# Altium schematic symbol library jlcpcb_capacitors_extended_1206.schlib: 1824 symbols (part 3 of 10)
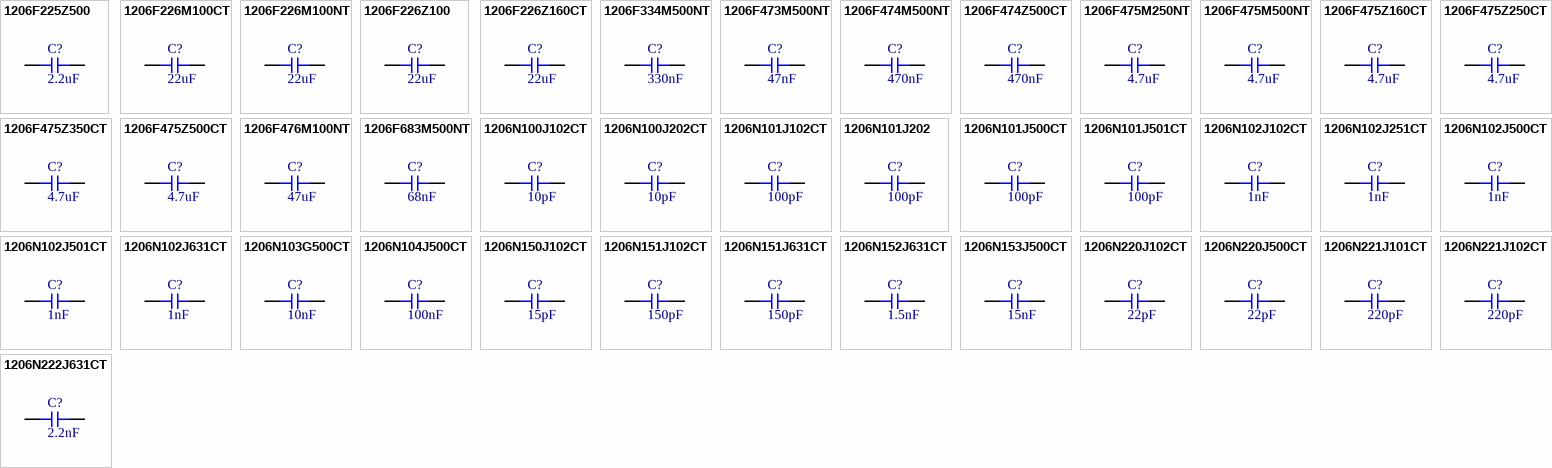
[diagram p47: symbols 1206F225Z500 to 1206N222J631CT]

## 1206N221J101CT
designator C?  Capacitance: 220pF  (hidden comment: *)
Capacitor, Ceramic (MLCC), 220pF, ±5%, 100V, NP0, ±5%, SMD 1206; Manufacturer: Walsin Tech Corp; Manufacturer Part Number: 1206N221J101CT
footprint CAP-1206 (1206 (3216M) Capacitor)
pins: 1, 2

## 1206N221J102CT
designator C?  Capacitance: 220pF  (hidden comment: *)
Capacitor, Ceramic (MLCC), 220pF, ±5%, 1kV, NP0, ±5%, SMD 1206; Manufacturer: Walsin Tech Corp; Manufacturer Part Number: 1206N221J102CT
footprint CAP-1206 (1206 (3216M) Capacitor)
pins: 1, 2

## 1206N222J631CT
designator C?  Capacitance: 2.2nF  (hidden comment: *)
Capacitor, Ceramic (MLCC), 2.2nF, ±5%, 630V, NP0, ±5%, SMD 1206; Manufacturer: Walsin Tech Corp; Manufacturer Part Number: 1206N222J631CT
footprint CAP-1206 (1206 (3216M) Capacitor)
pins: 1, 2

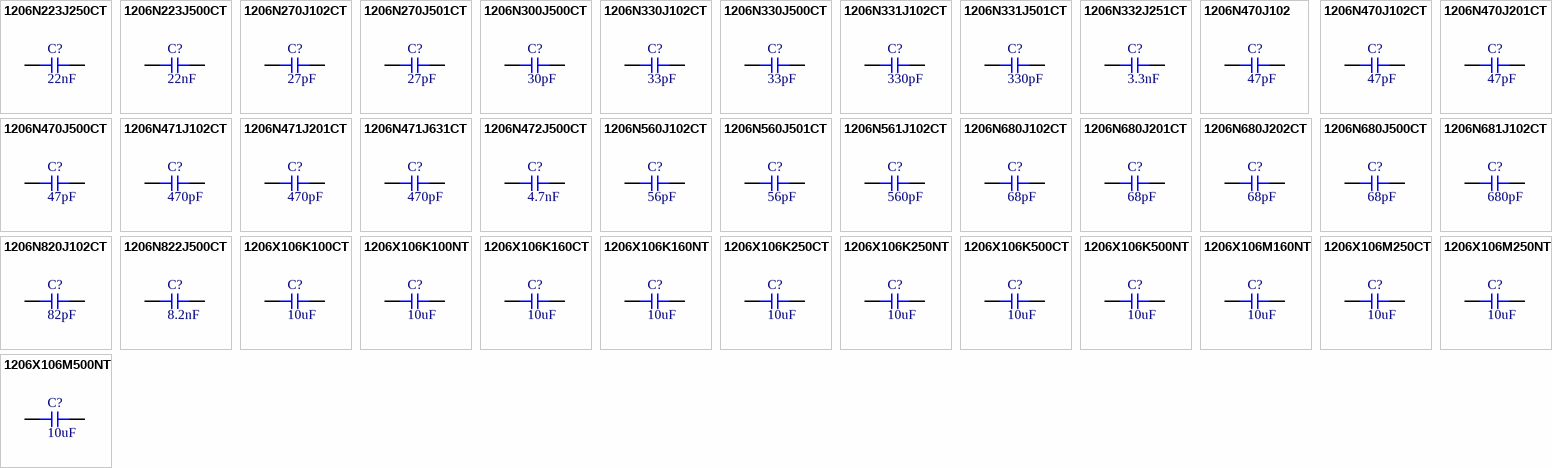
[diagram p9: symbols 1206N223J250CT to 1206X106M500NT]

## 1206N223J250CT
designator C?  Capacitance: 22nF  (hidden comment: *)
Capacitor, Ceramic (MLCC), 22nF, ±5%, 25V, NP0, ±5%, SMD 1206; Manufacturer: Walsin Tech Corp; Manufacturer Part Number: 1206N223J250CT
footprint CAP-1206 (1206 (3216M) Capacitor)
pins: 1, 2

## 1206N223J500CT
designator C?  Capacitance: 22nF  (hidden comment: *)
Capacitor, Ceramic (MLCC), 22nF, ±5%, 50V, NP0, ±5%, SMD 1206; Manufacturer: Walsin Tech Corp; Manufacturer Part Number: 1206N223J500CT
footprint CAP-1206 (1206 (3216M) Capacitor)
pins: 1, 2

## 1206N270J102CT
designator C?  Capacitance: 27pF  (hidden comment: *)
Capacitor, Ceramic (MLCC), 27pF, ±5%, 1kV, NP0, ±5%, SMD 1206; Manufacturer: Walsin Tech Corp; Manufacturer Part Number: 1206N270J102CT
footprint CAP-1206 (1206 (3216M) Capacitor)
pins: 1, 2

## 1206N270J501CT
designator C?  Capacitance: 27pF  (hidden comment: *)
Capacitor, Ceramic (MLCC), 27pF, ±5%, 500V, NP0, ±5%, SMD 1206; Manufacturer: Walsin Tech Corp; Manufacturer Part Number: 1206N270J501CT
footprint CAP-1206 (1206 (3216M) Capacitor)
pins: 1, 2

## 1206N300J500CT
designator C?  Capacitance: 30pF  (hidden comment: *)
Capacitor, Ceramic (MLCC), 30pF, ±5%, 50V, NP0, ±5%, SMD 1206; Manufacturer: Walsin Tech Corp; Manufacturer Part Number: 1206N300J500CT
footprint CAP-1206 (1206 (3216M) Capacitor)
pins: 1, 2

## 1206N330J102CT
designator C?  Capacitance: 33pF  (hidden comment: *)
Capacitor, Ceramic (MLCC), 33pF, ±5%, 1kV, NP0, ±5%, SMD 1206; Manufacturer: Walsin Tech Corp; Manufacturer Part Number: 1206N330J102CT
footprint CAP-1206 (1206 (3216M) Capacitor)
pins: 1, 2

## 1206N330J500CT
designator C?  Capacitance: 33pF  (hidden comment: *)
Capacitor, Ceramic (MLCC), 33pF, ±5%, 50V, NP0, ±5%, SMD 1206; Manufacturer: Walsin Tech Corp; Manufacturer Part Number: 1206N330J500CT
footprint CAP-1206 (1206 (3216M) Capacitor)
pins: 1, 2

## 1206N331J102CT
designator C?  Capacitance: 330pF  (hidden comment: *)
Capacitor, Ceramic (MLCC), 330pF, ±5%, 1kV, NP0, ±5%, SMD 1206; Manufacturer: Walsin Tech Corp; Manufacturer Part Number: 1206N331J102CT
footprint CAP-1206 (1206 (3216M) Capacitor)
pins: 1, 2

## 1206N331J501CT
designator C?  Capacitance: 330pF  (hidden comment: *)
Capacitor, Ceramic (MLCC), 330pF, ±5%, 500V, NP0, ±5%, SMD 1206; Manufacturer: Walsin Tech Corp; Manufacturer Part Number: 1206N331J501CT
footprint CAP-1206 (1206 (3216M) Capacitor)
pins: 1, 2

## 1206N332J251CT
designator C?  Capacitance: 3.3nF  (hidden comment: *)
Capacitor, Ceramic (MLCC), 3.3nF, ±5%, 250V, NP0, ±5%, SMD 1206; Manufacturer: Walsin Tech Corp; Manufacturer Part Number: 1206N332J251CT
footprint CAP-1206 (1206 (3216M) Capacitor)
pins: 1, 2

## 1206N470J102
designator C?  Capacitance: 47pF  (hidden comment: *)
Capacitor, Ceramic (MLCC), 47pF, ±5%, 1kV, NP0, ±5%, SMD 1206; Manufacturer: Walsin Tech Corp; Manufacturer Part Number: 1206N470J102
footprint CAP-1206 (1206 (3216M) Capacitor)
pins: 1, 2

## 1206N470J102CT
designator C?  Capacitance: 47pF  (hidden comment: *)
Capacitor, Ceramic (MLCC), 47pF, ±5%, 1kV, NP0, ±5%, SMD 1206; Manufacturer: Walsin Tech Corp; Manufacturer Part Number: 1206N470J102CT
footprint CAP-1206 (1206 (3216M) Capacitor)
pins: 1, 2

## 1206N470J201CT
designator C?  Capacitance: 47pF  (hidden comment: *)
Capacitor, Ceramic (MLCC), 47pF, ±5%, 200V, NP0, ±5%, SMD 1206; Manufacturer: Walsin Tech Corp; Manufacturer Part Number: 1206N470J201CT
footprint CAP-1206 (1206 (3216M) Capacitor)
pins: 1, 2

## 1206N470J500CT
designator C?  Capacitance: 47pF  (hidden comment: *)
Capacitor, Ceramic (MLCC), 47pF, ±5%, 50V, NP0, ±5%, SMD 1206; Manufacturer: Walsin Tech Corp; Manufacturer Part Number: 1206N470J500CT
footprint CAP-1206 (1206 (3216M) Capacitor)
pins: 1, 2

## 1206N471J102CT
designator C?  Capacitance: 470pF  (hidden comment: *)
Capacitor, Ceramic (MLCC), 470pF, ±5%, 1kV, NP0, ±5%, SMD 1206; Manufacturer: Walsin Tech Corp; Manufacturer Part Number: 1206N471J102CT
footprint CAP-1206 (1206 (3216M) Capacitor)
pins: 1, 2

## 1206N471J201CT
designator C?  Capacitance: 470pF  (hidden comment: *)
Capacitor, Ceramic (MLCC), 470pF, ±5%, 200V, NP0, ±5%, SMD 1206; Manufacturer: Walsin Tech Corp; Manufacturer Part Number: 1206N471J201CT
footprint CAP-1206 (1206 (3216M) Capacitor)
pins: 1, 2

## 1206N471J631CT
designator C?  Capacitance: 470pF  (hidden comment: *)
Capacitor, Ceramic (MLCC), 470pF, ±5%, 630V, NP0, ±5%, SMD 1206; Manufacturer: Walsin Tech Corp; Manufacturer Part Number: 1206N471J631CT
footprint CAP-1206 (1206 (3216M) Capacitor)
pins: 1, 2

## 1206N472J500CT
designator C?  Capacitance: 4.7nF  (hidden comment: *)
Capacitor, Ceramic (MLCC), 4.7nF, ±5%, 50V, NP0, ±5%, SMD 1206; Manufacturer: Walsin Tech Corp; Manufacturer Part Number: 1206N472J500CT
footprint CAP-1206 (1206 (3216M) Capacitor)
pins: 1, 2

## 1206N560J102CT
designator C?  Capacitance: 56pF  (hidden comment: *)
Capacitor, Ceramic (MLCC), 56pF, ±5%, 1kV, NP0, ±5%, SMD 1206; Manufacturer: Walsin Tech Corp; Manufacturer Part Number: 1206N560J102CT
footprint CAP-1206 (1206 (3216M) Capacitor)
pins: 1, 2

## 1206N560J501CT
designator C?  Capacitance: 56pF  (hidden comment: *)
Capacitor, Ceramic (MLCC), 56pF, ±5%, 500V, NP0, ±5%, SMD 1206; Manufacturer: Walsin Tech Corp; Manufacturer Part Number: 1206N560J501CT
footprint CAP-1206 (1206 (3216M) Capacitor)
pins: 1, 2

## 1206N561J102CT
designator C?  Capacitance: 560pF  (hidden comment: *)
Capacitor, Ceramic (MLCC), 560pF, ±5%, 1kV, NP0, ±5%, SMD 1206; Manufacturer: Walsin Tech Corp; Manufacturer Part Number: 1206N561J102CT
footprint CAP-1206 (1206 (3216M) Capacitor)
pins: 1, 2

## 1206N680J102CT
designator C?  Capacitance: 68pF  (hidden comment: *)
Capacitor, Ceramic (MLCC), 68pF, ±5%, 1kV, NP0, ±5%, SMD 1206; Manufacturer: Walsin Tech Corp; Manufacturer Part Number: 1206N680J102CT
footprint CAP-1206 (1206 (3216M) Capacitor)
pins: 1, 2

## 1206N680J201CT
designator C?  Capacitance: 68pF  (hidden comment: *)
Capacitor, Ceramic (MLCC), 68pF, ±5%, 200V, NP0, ±5%, SMD 1206; Manufacturer: Walsin Tech Corp; Manufacturer Part Number: 1206N680J201CT
footprint CAP-1206 (1206 (3216M) Capacitor)
pins: 1, 2

## 1206N680J202CT
designator C?  Capacitance: 68pF  (hidden comment: *)
Capacitor, Ceramic (MLCC), 68pF, ±5%, 2kV, NP0, ±5%, SMD 1206; Manufacturer: Walsin Tech Corp; Manufacturer Part Number: 1206N680J202CT
footprint CAP-1206 (1206 (3216M) Capacitor)
pins: 1, 2

## 1206N680J500CT
designator C?  Capacitance: 68pF  (hidden comment: *)
Capacitor, Ceramic (MLCC), 68pF, ±5%, 50V, NP0, ±5%, SMD 1206; Manufacturer: Walsin Tech Corp; Manufacturer Part Number: 1206N680J500CT
footprint CAP-1206 (1206 (3216M) Capacitor)
pins: 1, 2

## 1206N681J102CT
designator C?  Capacitance: 680pF  (hidden comment: *)
Capacitor, Ceramic (MLCC), 680pF, ±5%, 1kV, NP0, ±5%, SMD 1206; Manufacturer: Walsin Tech Corp; Manufacturer Part Number: 1206N681J102CT
footprint CAP-1206 (1206 (3216M) Capacitor)
pins: 1, 2

## 1206N820J102CT
designator C?  Capacitance: 82pF  (hidden comment: *)
Capacitor, Ceramic (MLCC), 82pF, ±5%, 1kV, NP0, ±5%, SMD 1206; Manufacturer: Walsin Tech Corp; Manufacturer Part Number: 1206N820J102CT
footprint CAP-1206 (1206 (3216M) Capacitor)
pins: 1, 2

## 1206N822J500CT
designator C?  Capacitance: 8.2nF  (hidden comment: *)
Capacitor, Ceramic (MLCC), 8.2nF, ±5%, 50V, NP0, ±5%, SMD 1206; Manufacturer: Walsin Tech Corp; Manufacturer Part Number: 1206N822J500CT
footprint CAP-1206 (1206 (3216M) Capacitor)
pins: 1, 2

## 1206X106K100CT
designator C?  Capacitance: 10uF  (hidden comment: *)
Capacitor, Ceramic (MLCC), 10uF, ±10%, 10V, X5R, ±10%, SMD 1206; Manufacturer: Walsin Tech Corp; Manufacturer Part Number: 1206X106K100CT
footprint CAP-1206 (1206 (3216M) Capacitor)
pins: 1, 2

## 1206X106K100NT
designator C?  Capacitance: 10uF  (hidden comment: *)
Capacitor, Ceramic (MLCC), 10uF, ±10%, 10V, X5R, ±10%, SMD 1206; Manufacturer: FH(Guangdong Fenghua Advanced Tech); Manufacturer Part Number: 1206X106K100NT
footprint CAP-1206 (1206 (3216M) Capacitor)
pins: 1, 2

## 1206X106K160CT
designator C?  Capacitance: 10uF  (hidden comment: *)
Capacitor, Ceramic (MLCC), 10uF, ±10%, 16V, X5R, ±10%, SMD 1206; Manufacturer: Walsin Tech Corp; Manufacturer Part Number: 1206X106K160CT
footprint CAP-1206 (1206 (3216M) Capacitor)
pins: 1, 2

## 1206X106K160NT
designator C?  Capacitance: 10uF  (hidden comment: *)
Capacitor, Ceramic (MLCC), 10uF, ±10%, 16V, X5R, ±10%, SMD 1206; Manufacturer: FH(Guangdong Fenghua Advanced Tech); Manufacturer Part Number: 1206X106K160NT
footprint CAP-1206 (1206 (3216M) Capacitor)
pins: 1, 2

## 1206X106K250CT
designator C?  Capacitance: 10uF  (hidden comment: *)
Capacitor, Ceramic (MLCC), 10uF, ±10%, 25V, X5R, ±10%, SMD 1206; Manufacturer: Walsin Tech Corp; Manufacturer Part Number: 1206X106K250CT
footprint CAP-1206 (1206 (3216M) Capacitor)
pins: 1, 2

## 1206X106K250NT
designator C?  Capacitance: 10uF  (hidden comment: *)
Capacitor, Ceramic (MLCC), 10uF, ±10%, 25V, X5R, ±10%, SMD 1206; Manufacturer: FH(Guangdong Fenghua Advanced Tech); Manufacturer Part Number: 1206X106K250NT
footprint CAP-1206 (1206 (3216M) Capacitor)
pins: 1, 2

## 1206X106K500CT
designator C?  Capacitance: 10uF  (hidden comment: *)
Capacitor, Ceramic (MLCC), 10uF, ±10%, 50V, X5R, ±10%, SMD 1206; Manufacturer: Walsin Tech Corp; Manufacturer Part Number: 1206X106K500CT
footprint CAP-1206 (1206 (3216M) Capacitor)
pins: 1, 2

## 1206X106K500NT
designator C?  Capacitance: 10uF  (hidden comment: *)
Capacitor, Ceramic (MLCC), 10uF, ±10%, 50V, X5R, ±10%, SMD 1206; Manufacturer: FH(Guangdong Fenghua Advanced Tech); Manufacturer Part Number: 1206X106K500NT
footprint CAP-1206 (1206 (3216M) Capacitor)
pins: 1, 2

## 1206X106M160NT
designator C?  Capacitance: 10uF  (hidden comment: *)
Capacitor, Ceramic (MLCC), 10uF, ±20%, 16V, X5R, ±20%, SMD 1206; Manufacturer: FH(Guangdong Fenghua Advanced Tech); Manufacturer Part Number: 1206X106M160NT
footprint CAP-1206 (1206 (3216M) Capacitor)
pins: 1, 2

## 1206X106M250CT
designator C?  Capacitance: 10uF  (hidden comment: *)
Capacitor, Ceramic (MLCC), 10uF, ±20%, 25V, X5R, ±20%, SMD 1206; Manufacturer: Walsin Tech Corp; Manufacturer Part Number: 1206X106M250CT
footprint CAP-1206 (1206 (3216M) Capacitor)
pins: 1, 2

## 1206X106M250NT
designator C?  Capacitance: 10uF  (hidden comment: *)
Capacitor, Ceramic (MLCC), 10uF, ±20%, 25V, X5R, ±20%, SMD 1206; Manufacturer: FH(Guangdong Fenghua Advanced Tech); Manufacturer Part Number: 1206X106M250NT
footprint CAP-1206 (1206 (3216M) Capacitor)
pins: 1, 2

## 1206X106M500NT
designator C?  Capacitance: 10uF  (hidden comment: *)
Capacitor, Ceramic (MLCC), 10uF, ±20%, 50V, X5R, ±20%, SMD 1206; Manufacturer: FH(Guangdong Fenghua Advanced Tech); Manufacturer Part Number: 1206X106M500NT
footprint CAP-1206 (1206 (3216M) Capacitor)
pins: 1, 2

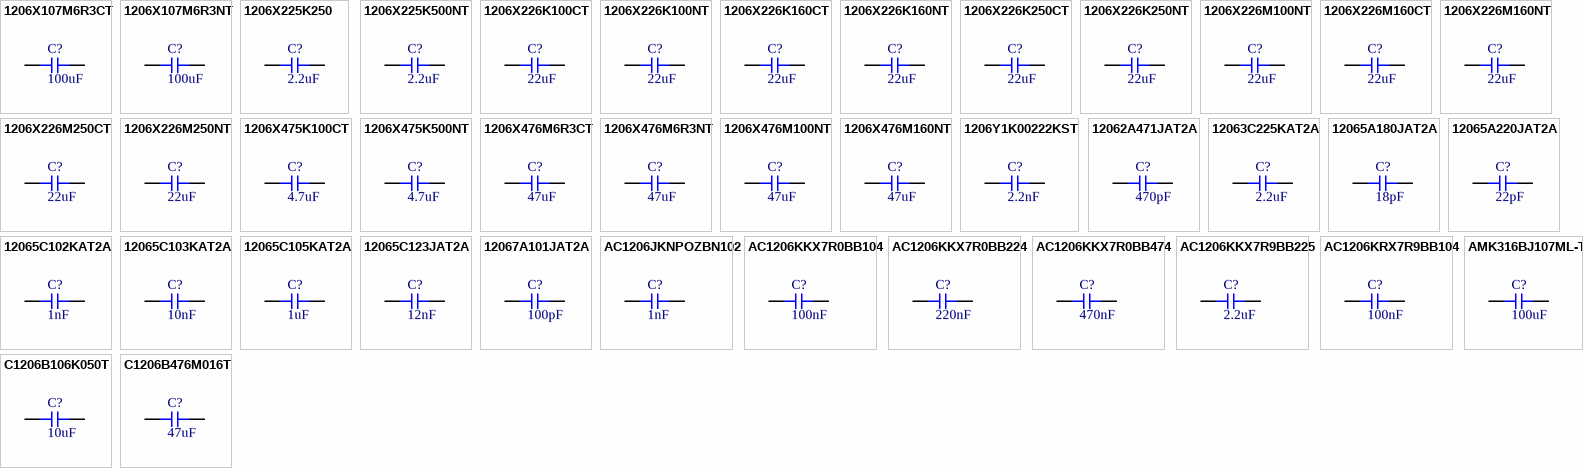
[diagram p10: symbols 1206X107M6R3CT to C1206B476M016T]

## 1206X107M6R3CT
designator C?  Capacitance: 100uF  (hidden comment: *)
Capacitor, Ceramic (MLCC), 100uF, ±20%, 6.3V, X5R, ±20%, SMD 1206; Manufacturer: Walsin Tech Corp; Manufacturer Part Number: 1206X107M6R3CT
footprint CAP-1206 (1206 (3216M) Capacitor)
pins: 1, 2

## 1206X107M6R3NT
designator C?  Capacitance: 100uF  (hidden comment: *)
Capacitor, Ceramic (MLCC), 100uF, ±20%, 6.3V, X5R, ±20%, SMD 1206; Manufacturer: FH(Guangdong Fenghua Advanced Tech); Manufacturer Part Number: 1206X107M6R3NT
footprint CAP-1206 (1206 (3216M) Capacitor)
pins: 1, 2

## 1206X225K250
designator C?  Capacitance: 2.2uF  (hidden comment: *)
Capacitor, Ceramic (MLCC), 2.2uF, ±10%, 25V, X5R, ±10%, SMD 1206; Manufacturer: Walsin Tech Corp; Manufacturer Part Number: 1206X225K250
footprint CAP-1206 (1206 (3216M) Capacitor)
pins: 1, 2

## 1206X225K500NT
designator C?  Capacitance: 2.2uF  (hidden comment: *)
Capacitor, Ceramic (MLCC), 2.2uF, ±10%, 50V, X5R, ±10%, SMD 1206; Manufacturer: FH(Guangdong Fenghua Advanced Tech); Manufacturer Part Number: 1206X225K500NT
footprint CAP-1206 (1206 (3216M) Capacitor)
pins: 1, 2

## 1206X226K100CT
designator C?  Capacitance: 22uF  (hidden comment: *)
Capacitor, Ceramic (MLCC), 22uF, ±10%, 10V, X5R, ±10%, SMD 1206; Manufacturer: Walsin Tech Corp; Manufacturer Part Number: 1206X226K100CT
footprint CAP-1206 (1206 (3216M) Capacitor)
pins: 1, 2

## 1206X226K100NT
designator C?  Capacitance: 22uF  (hidden comment: *)
Capacitor, Ceramic (MLCC), 22uF, ±10%, 10V, X5R, ±10%, SMD 1206; Manufacturer: FH(Guangdong Fenghua Advanced Tech); Manufacturer Part Number: 1206X226K100NT
footprint CAP-1206 (1206 (3216M) Capacitor)
pins: 1, 2

## 1206X226K160CT
designator C?  Capacitance: 22uF  (hidden comment: *)
Capacitor, Ceramic (MLCC), 22uF, ±10%, 16V, X5R, ±10%, SMD 1206; Manufacturer: Walsin Tech Corp; Manufacturer Part Number: 1206X226K160CT
footprint CAP-1206 (1206 (3216M) Capacitor)
pins: 1, 2

## 1206X226K160NT
designator C?  Capacitance: 22uF  (hidden comment: *)
Capacitor, Ceramic (MLCC), 22uF, ±10%, 16V, X5R, ±10%, SMD 1206; Manufacturer: FH(Guangdong Fenghua Advanced Tech); Manufacturer Part Number: 1206X226K160NT
footprint CAP-1206 (1206 (3216M) Capacitor)
pins: 1, 2

## 1206X226K250CT
designator C?  Capacitance: 22uF  (hidden comment: *)
Capacitor, Ceramic (MLCC), 22uF, ±10%, 25V, X5R, ±10%, SMD 1206; Manufacturer: Walsin Tech Corp; Manufacturer Part Number: 1206X226K250CT
footprint CAP-1206 (1206 (3216M) Capacitor)
pins: 1, 2

## 1206X226K250NT
designator C?  Capacitance: 22uF  (hidden comment: *)
Capacitor, Ceramic (MLCC), 22uF, ±10%, 25V, X5R, ±10%, SMD 1206; Manufacturer: FH (Guangdong Fenghua Advanced Tech); Manufacturer Part Number: 1206X226K250NT
footprint CAP-1206 (1206 (3216M) Capacitor)
pins: 1, 2

## 1206X226M100NT
designator C?  Capacitance: 22uF  (hidden comment: *)
Capacitor, Ceramic (MLCC), 22uF, ±20%, 10V, X5R, ±20%, SMD 1206; Manufacturer: FH(Guangdong Fenghua Advanced Tech); Manufacturer Part Number: 1206X226M100NT
footprint CAP-1206 (1206 (3216M) Capacitor)
pins: 1, 2

## 1206X226M160CT
designator C?  Capacitance: 22uF  (hidden comment: *)
Capacitor, Ceramic (MLCC), 22uF, ±20%, 16V, X5R, ±20%, SMD 1206; Manufacturer: Walsin Tech Corp; Manufacturer Part Number: 1206X226M160CT
footprint CAP-1206 (1206 (3216M) Capacitor)
pins: 1, 2

## 1206X226M160NT
designator C?  Capacitance: 22uF  (hidden comment: *)
Capacitor, Ceramic (MLCC), 22uF, ±20%, 16V, X5R, ±20%, SMD 1206; Manufacturer: FH(Guangdong Fenghua Advanced Tech); Manufacturer Part Number: 1206X226M160NT
footprint CAP-1206 (1206 (3216M) Capacitor)
pins: 1, 2

## 1206X226M250CT
designator C?  Capacitance: 22uF  (hidden comment: *)
Capacitor, Ceramic (MLCC), 22uF, ±20%, 25V, X5R, ±20%, SMD 1206; Manufacturer: Walsin Tech Corp; Manufacturer Part Number: 1206X226M250CT
footprint CAP-1206 (1206 (3216M) Capacitor)
pins: 1, 2

## 1206X226M250NT
designator C?  Capacitance: 22uF  (hidden comment: *)
Capacitor, Ceramic (MLCC), 22uF, ±20%, 25V, ±20%, SMD 1206; Manufacturer: FH(Guangdong Fenghua Advanced Tech); Manufacturer Part Number: 1206X226M250NT
footprint CAP-1206 (1206 (3216M) Capacitor)
pins: 1, 2

## 1206X475K100CT
designator C?  Capacitance: 4.7uF  (hidden comment: *)
Capacitor, Ceramic (MLCC), 4.7uF, ±10%, 10V, X5R, ±10%, SMD 1206; Manufacturer: Walsin Tech Corp; Manufacturer Part Number: 1206X475K100CT
footprint CAP-1206 (1206 (3216M) Capacitor)
pins: 1, 2

## 1206X475K500NT
designator C?  Capacitance: 4.7uF  (hidden comment: *)
Capacitor, Ceramic (MLCC), 4.7uF, ±10%, 50V, X5R, ±10%, SMD 1206; Manufacturer: FH(Guangdong Fenghua Advanced Tech); Manufacturer Part Number: 1206X475K500NT
footprint CAP-1206 (1206 (3216M) Capacitor)
pins: 1, 2

## 1206X476M6R3CT
designator C?  Capacitance: 47uF  (hidden comment: *)
Capacitor, Ceramic (MLCC), 47uF, ±20%, 6.3V, X5R, ±20%, SMD 1206; Manufacturer: Walsin Tech Corp; Manufacturer Part Number: 1206X476M6R3CT
footprint CAP-1206 (1206 (3216M) Capacitor)
pins: 1, 2

## 1206X476M6R3NT
designator C?  Capacitance: 47uF  (hidden comment: *)
Capacitor, Ceramic (MLCC), 47uF, ±20%, 6.3V, X5R, ±20%, SMD 1206; Manufacturer: FH(Guangdong Fenghua Advanced Tech); Manufacturer Part Number: 1206X476M6R3NT
footprint CAP-1206 (1206 (3216M) Capacitor)
pins: 1, 2

## 1206X476M100NT
designator C?  Capacitance: 47uF  (hidden comment: *)
Capacitor, Ceramic (MLCC), 47uF, ±20%, 10V, X5R, ±20%, SMD 1206; Manufacturer: FH(Guangdong Fenghua Advanced Tech); Manufacturer Part Number: 1206X476M100NT
footprint CAP-1206 (1206 (3216M) Capacitor)
pins: 1, 2

## 1206X476M160NT
designator C?  Capacitance: 47uF  (hidden comment: *)
Capacitor, Ceramic (MLCC), 47uF, ±20%, 16V, X5R, ±20%, SMD 1206; Manufacturer: FH(Guangdong Fenghua Advanced Tech); Manufacturer Part Number: 1206X476M160NT
footprint CAP-1206 (1206 (3216M) Capacitor)
pins: 1, 2

## 1206Y1K00222KST
designator C?  Capacitance: 2.2nF  (hidden comment: *)
Capacitor, Ceramic (MLCC), 2.2nF, ±10%, 1kV, X7R, ±10%, SMD 1206; Manufacturer: Knowles; Manufacturer Part Number: 1206Y1K00222KST
footprint CAP-1206 (1206 (3216M) Capacitor)
pins: 1, 2

## 12062A471JAT2A
designator C?  Capacitance: 470pF  (hidden comment: *)
Capacitor, Ceramic (MLCC), 470pF, ±5%, 200V, C0G, ±5%, SMD 1206; Manufacturer: AVX; Manufacturer Part Number: 12062A471JAT2A
footprint CAP-1206 (1206 (3216M) Capacitor)
pins: 1, 2

## 12063C225KAT2A
designator C?  Capacitance: 2.2uF  (hidden comment: *)
Capacitor, Ceramic (MLCC), 2.2uF, ±10%, 25V, X7R, ±10%, SMD 1206; Manufacturer: AVX; Manufacturer Part Number: 12063C225KAT2A
footprint CAP-1206 (1206 (3216M) Capacitor)
pins: 1, 2

## 12065A180JAT2A
designator C?  Capacitance: 18pF  (hidden comment: *)
Capacitor, Ceramic (MLCC), 18pF, ±5%, 50V, C0G, ±5%, SMD 1206; Manufacturer: AVX; Manufacturer Part Number: 12065A180JAT2A
footprint CAP-1206 (1206 (3216M) Capacitor)
pins: 1, 2

## 12065A220JAT2A
designator C?  Capacitance: 22pF  (hidden comment: *)
Capacitor, Ceramic (MLCC), 22pF, ±5%, 50V, C0G, ±5%, SMD 1206; Manufacturer: AVX; Manufacturer Part Number: 12065A220JAT2A
footprint CAP-1206 (1206 (3216M) Capacitor)
pins: 1, 2

## 12065C102KAT2A
designator C?  Capacitance: 1nF  (hidden comment: *)
Capacitor, Ceramic (MLCC), 1nF, ±10%, 50V, X7R, ±10%, SMD 1206; Manufacturer: AVX; Manufacturer Part Number: 12065C102KAT2A
footprint CAP-1206 (1206 (3216M) Capacitor)
pins: 1, 2

## 12065C103KAT2A
designator C?  Capacitance: 10nF  (hidden comment: *)
Capacitor, Ceramic (MLCC), 10nF, ±10%, 50V, X7R, ±10%, SMD 1206; Manufacturer: Kyocera AVX; Manufacturer Part Number: 12065C103KAT2A
footprint CAP-1206 (1206 (3216M) Capacitor)
pins: 1, 2

## 12065C105KAT2A
designator C?  Capacitance: 1uF  (hidden comment: *)
Capacitor, Ceramic (MLCC), 1uF, ±10%, 50V, X7R, ±10%, SMD 1206; Manufacturer: AVX; Manufacturer Part Number: 12065C105KAT2A
footprint CAP-1206 (1206 (3216M) Capacitor)
pins: 1, 2

## 12065C123JAT2A
designator C?  Capacitance: 12nF  (hidden comment: *)
Capacitor, Ceramic (MLCC), 12nF, ±5%, 50V, X7R, ±5%, SMD 1206; Manufacturer: AVX; Manufacturer Part Number: 12065C123JAT2A
footprint CAP-1206 (1206 (3216M) Capacitor)
pins: 1, 2

## 12067A101JAT2A
designator C?  Capacitance: 100pF  (hidden comment: *)
Capacitor, Ceramic (MLCC), 100pF, ±5%, 500V, C0G, ±5%, SMD 1206; Manufacturer: AVX; Manufacturer Part Number: 12067A101JAT2A
footprint CAP-1206 (1206 (3216M) Capacitor)
pins: 1, 2

## AC1206JKNPOZBN102
designator C?  Capacitance: 1nF  (hidden comment: *)
Capacitor, Ceramic (MLCC), 1nF, ±5%, 630V, NP0, ±5%, SMD 1206; Manufacturer: YAGEO; Manufacturer Part Number: AC1206JKNPOZBN102
footprint CAP-1206 (1206 (3216M) Capacitor)
pins: 1, 2

## AC1206KKX7R0BB104
designator C?  Capacitance: 100nF  (hidden comment: *)
Capacitor, Ceramic (MLCC), 100nF, ±10%, 100V, X7R, ±10%, SMD 1206; Manufacturer: YAGEO; Manufacturer Part Number: AC1206KKX7R0BB104
footprint CAP-1206 (1206 (3216M) Capacitor)
pins: 1, 2

## AC1206KKX7R0BB224
designator C?  Capacitance: 220nF  (hidden comment: *)
Capacitor, Ceramic (MLCC), 220nF, ±10%, 100V, X7R, ±10%, SMD 1206; Manufacturer: YAGEO; Manufacturer Part Number: AC1206KKX7R0BB224
footprint CAP-1206 (1206 (3216M) Capacitor)
pins: 1, 2

## AC1206KKX7R0BB474
designator C?  Capacitance: 470nF  (hidden comment: *)
Capacitor, Ceramic (MLCC), 470nF, ±10%, 100V, X7R, ±10%, SMD 1206; Manufacturer: YAGEO; Manufacturer Part Number: AC1206KKX7R0BB474
footprint CAP-1206 (1206 (3216M) Capacitor)
pins: 1, 2

## AC1206KKX7R9BB225
designator C?  Capacitance: 2.2uF  (hidden comment: *)
Capacitor, Ceramic (MLCC), 2.2uF, ±10%, 50V, X7R, ±10%, SMD 1206; Manufacturer: YAGEO; Manufacturer Part Number: AC1206KKX7R9BB225
footprint CAP-1206 (1206 (3216M) Capacitor)
pins: 1, 2

## AC1206KRX7R9BB104
designator C?  Capacitance: 100nF  (hidden comment: *)
Capacitor, Ceramic (MLCC), 100nF, ±10%, 50V, X7R, ±10%, SMD 1206; Manufacturer: YAGEO; Manufacturer Part Number: AC1206KRX7R9BB104
footprint CAP-1206 (1206 (3216M) Capacitor)
pins: 1, 2

## AMK316BJ107ML-T
designator C?  Capacitance: 100uF  (hidden comment: *)
Capacitor, Ceramic (MLCC), 100uF, ±20%, 4V, X5R, ±20%, SMD 1206; Manufacturer: Taiyo Yuden; Manufacturer Part Number: AMK316BJ107ML-T
footprint CAP-1206 (1206 (3216M) Capacitor)
pins: 1, 2

## C1206B106K050T
designator C?  Capacitance: 10uF  (hidden comment: *)
Capacitor, Ceramic (MLCC), 10uF, ±10%, 50V, X5R, ±10%, SMD 1206; Manufacturer: IHHEC(HOLY STONE ENTERPRISE CO., LTD); Manufacturer Part Number: C1206B106K050T
footprint CAP-1206 (1206 (3216M) Capacitor)
pins: 1, 2

## C1206B476M016T
designator C?  Capacitance: 47uF  (hidden comment: *)
Capacitor, Ceramic (MLCC), 47uF, ±20%, 16V, ±20%, SMD 1206; Manufacturer: IHHEC(HOLY STONE ENTERPRISE CO., LTD); Manufacturer Part Number: C1206B476M016T
footprint CAP-1206 (1206 (3216M) Capacitor)
pins: 1, 2

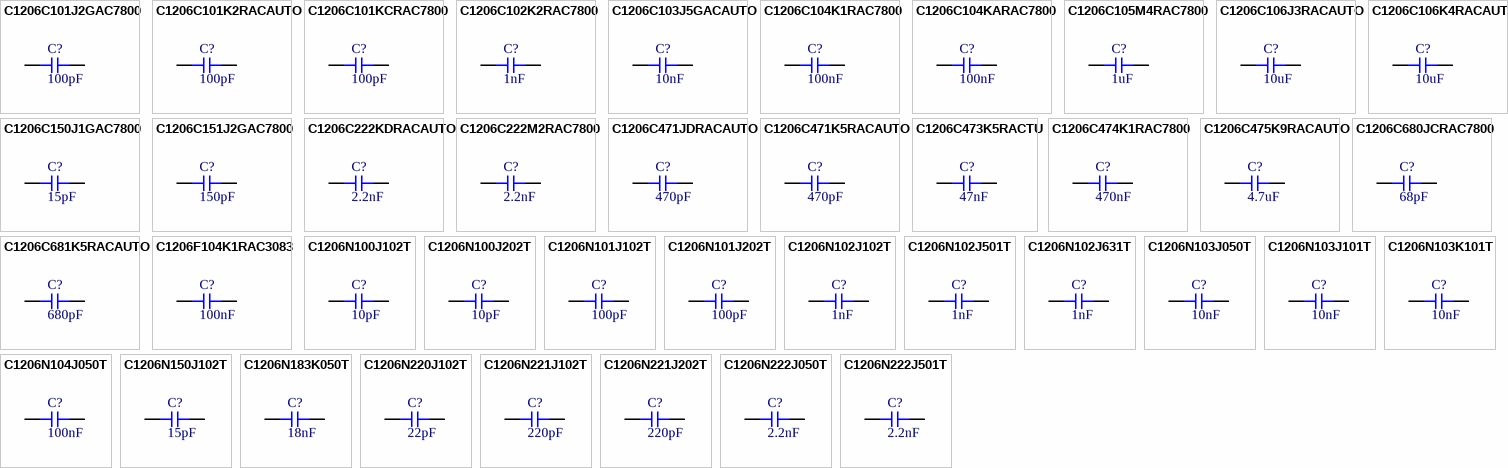
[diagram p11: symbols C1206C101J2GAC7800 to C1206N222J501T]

## C1206C101J2GAC7800
designator C?  Capacitance: 100pF  (hidden comment: *)
Capacitor, Ceramic (MLCC), 100pF, ±5%, 200V, C0G, ±5%, SMD 1206; Manufacturer: KEMET; Manufacturer Part Number: C1206C101J2GAC7800
footprint CAP-1206 (1206 (3216M) Capacitor)
pins: 1, 2

## C1206C101K2RACAUTO
designator C?  Capacitance: 100pF  (hidden comment: *)
Capacitor, Ceramic (MLCC), 100pF, ±10%, 200V, X7R, ±10%, SMD 1206; Manufacturer: KEMET; Manufacturer Part Number: C1206C101K2RACAUTO
footprint CAP-1206 (1206 (3216M) Capacitor)
pins: 1, 2

## C1206C101KCRAC7800
designator C?  Capacitance: 100pF  (hidden comment: *)
Capacitor, Ceramic (MLCC), 100pF, ±10%, 500V, X7R, ±10%, SMD 1206; Manufacturer: KEMET; Manufacturer Part Number: C1206C101KCRAC7800
footprint CAP-1206 (1206 (3216M) Capacitor)
pins: 1, 2

## C1206C102K2RAC7800
designator C?  Capacitance: 1nF  (hidden comment: *)
Capacitor, Ceramic (MLCC), 1nF, ±10%, 200V, X7R, ±10%, SMD 1206; Manufacturer: KEMET; Manufacturer Part Number: C1206C102K2RAC7800
footprint CAP-1206 (1206 (3216M) Capacitor)
pins: 1, 2

## C1206C103J5GACAUTO
designator C?  Capacitance: 10nF  (hidden comment: *)
Capacitor, Ceramic (MLCC), 10nF, ±5%, 50V, C0G, ±5%, SMD 1206; Manufacturer: KEMET; Manufacturer Part Number: C1206C103J5GACAUTO
footprint CAP-1206 (1206 (3216M) Capacitor)
pins: 1, 2

## C1206C104K1RAC7800
designator C?  Capacitance: 100nF  (hidden comment: *)
Capacitor, Ceramic (MLCC), 100nF, ±10%, 100V, X7R, ±10%, SMD 1206; Manufacturer: KEMET; Manufacturer Part Number: C1206C104K1RAC7800
footprint CAP-1206 (1206 (3216M) Capacitor)
pins: 1, 2

## C1206C104KARAC7800
designator C?  Capacitance: 100nF  (hidden comment: *)
Capacitor, Ceramic (MLCC), 100nF, ±10%, 250V, X7R, ±10%, SMD 1206; Manufacturer: KEMET; Manufacturer Part Number: C1206C104KARAC7800
footprint CAP-1206 (1206 (3216M) Capacitor)
pins: 1, 2

## C1206C105M4RAC7800
designator C?  Capacitance: 1uF  (hidden comment: *)
Capacitor, Ceramic (MLCC), 1uF, ±20%, 16V, X7R, ±20%, SMD 1206; Manufacturer: KEMET; Manufacturer Part Number: C1206C105M4RAC7800
footprint CAP-1206 (1206 (3216M) Capacitor)
pins: 1, 2

## C1206C106J3RACAUTO
designator C?  Capacitance: 10uF  (hidden comment: *)
Capacitor, Ceramic (MLCC), 10uF, ±5%, 25V, X7R, ±5%, SMD 1206; Manufacturer: KEMET; Manufacturer Part Number: C1206C106J3RACAUTO
footprint CAP-1206 (1206 (3216M) Capacitor)
pins: 1, 2

## C1206C106K4RACAUTO
designator C?  Capacitance: 10uF  (hidden comment: *)
Capacitor, Ceramic (MLCC), 10uF, ±10%, 16V, X7R, ±10%, SMD 1206; Manufacturer: KEMET; Manufacturer Part Number: C1206C106K4RACAUTO
footprint CAP-1206 (1206 (3216M) Capacitor)
pins: 1, 2

## C1206C150J1GAC7800
designator C?  Capacitance: 15pF  (hidden comment: *)
Capacitor, Ceramic (MLCC), 15pF, ±5%, 100V, C0G, ±5%, SMD 1206; Manufacturer: KEMET; Manufacturer Part Number: C1206C150J1GAC7800
footprint CAP-1206 (1206 (3216M) Capacitor)
pins: 1, 2

## C1206C151J2GAC7800
designator C?  Capacitance: 150pF  (hidden comment: *)
Capacitor, Ceramic (MLCC), 150pF, ±5%, 200V, C0G, ±5%, SMD 1206; Manufacturer: KEMET; Manufacturer Part Number: C1206C151J2GAC7800
footprint CAP-1206 (1206 (3216M) Capacitor)
pins: 1, 2

## C1206C222KDRACAUTO
designator C?  Capacitance: 2.2nF  (hidden comment: *)
Capacitor, Ceramic (MLCC), 2.2nF, ±10%, 1kV, X7R, ±10%, SMD 1206; Manufacturer: KEMET; Manufacturer Part Number: C1206C222KDRACAUTO
footprint CAP-1206 (1206 (3216M) Capacitor)
pins: 1, 2

## C1206C222M2RAC7800
designator C?  Capacitance: 2.2nF  (hidden comment: *)
Capacitor, Ceramic (MLCC), 2.2nF, ±20%, 200V, X7R, ±20%, SMD 1206; Manufacturer: KEMET; Manufacturer Part Number: C1206C222M2RAC7800
footprint CAP-1206 (1206 (3216M) Capacitor)
pins: 1, 2

## C1206C471JDRACAUTO
designator C?  Capacitance: 470pF  (hidden comment: *)
Capacitor, Ceramic (MLCC), 470pF, ±5%, 1kV, X7R, ±5%, SMD 1206; Manufacturer: KEMET; Manufacturer Part Number: C1206C471JDRACAUTO
footprint CAP-1206 (1206 (3216M) Capacitor)
pins: 1, 2

## C1206C471K5RACAUTO
designator C?  Capacitance: 470pF  (hidden comment: *)
Capacitor, Ceramic (MLCC), 470pF, ±10%, 50V, X7R, ±10%, SMD 1206; Manufacturer: KEMET; Manufacturer Part Number: C1206C471K5RACAUTO
footprint CAP-1206 (1206 (3216M) Capacitor)
pins: 1, 2

## C1206C473K5RACTU
designator C?  Capacitance: 47nF  (hidden comment: *)
Capacitor, Ceramic (MLCC), 47nF, ±10%, 50V, X7R, ±10%, SMD 1206; Manufacturer: KEMET; Manufacturer Part Number: C1206C473K5RACTU
footprint CAP-1206 (1206 (3216M) Capacitor)
pins: 1, 2

## C1206C474K1RAC7800
designator C?  Capacitance: 470nF  (hidden comment: *)
Capacitor, Ceramic (MLCC), 470nF, ±10%, 100V, X7R, ±10%, SMD 1206; Manufacturer: KEMET; Manufacturer Part Number: C1206C474K1RAC7800
footprint CAP-1206 (1206 (3216M) Capacitor)
pins: 1, 2

## C1206C475K9RACAUTO
designator C?  Capacitance: 4.7uF  (hidden comment: *)
Capacitor, Ceramic (MLCC), 4.7uF, ±10%, 6.3V, X7R, ±10%, SMD 1206; Manufacturer: KEMET; Manufacturer Part Number: C1206C475K9RACAUTO
footprint CAP-1206 (1206 (3216M) Capacitor)
pins: 1, 2

## C1206C680JCRAC7800
designator C?  Capacitance: 68pF  (hidden comment: *)
Capacitor, Ceramic (MLCC), 68pF, ±5%, 500V, X7R, ±5%, SMD 1206; Manufacturer: KEMET; Manufacturer Part Number: C1206C680JCRAC7800
footprint CAP-1206 (1206 (3216M) Capacitor)
pins: 1, 2

## C1206C681K5RACAUTO
designator C?  Capacitance: 680pF  (hidden comment: *)
Capacitor, Ceramic (MLCC), 680pF, ±10%, 50V, X7R, ±10%, SMD 1206; Manufacturer: KEMET; Manufacturer Part Number: C1206C681K5RACAUTO
footprint CAP-1206 (1206 (3216M) Capacitor)
pins: 1, 2

## C1206F104K1RAC3083
designator C?  Capacitance: 100nF  (hidden comment: *)
Capacitor, Ceramic (MLCC), 100nF, ±10%, 100V, X7R, ±10%, SMD 1206; Manufacturer: KEMET; Manufacturer Part Number: C1206F104K1RAC3083
footprint CAP-1206 (1206 (3216M) Capacitor)
pins: 1, 2

## C1206N100J102T
designator C?  Capacitance: 10pF  (hidden comment: *)
Capacitor, Ceramic (MLCC), 10pF, ±5%, 1kV, C0G, ±5%, SMD 1206; Manufacturer: IHHEC(HOLY STONE ENTERPRISE CO., LTD); Manufacturer Part Number: C1206N100J102T
footprint CAP-1206 (1206 (3216M) Capacitor)
pins: 1, 2

## C1206N100J202T
designator C?  Capacitance: 10pF  (hidden comment: *)
Capacitor, Ceramic (MLCC), 10pF, ±5%, 2kV, C0G, ±5%, SMD 1206; Manufacturer: IHHEC(HOLY STONE ENTERPRISE CO., LTD); Manufacturer Part Number: C1206N100J202T
footprint CAP-1206 (1206 (3216M) Capacitor)
pins: 1, 2

## C1206N101J102T
designator C?  Capacitance: 100pF  (hidden comment: *)
Capacitor, Ceramic (MLCC), 100pF, ±5%, 1kV, C0G, ±5%, SMD 1206; Manufacturer: IHHEC(HOLY STONE ENTERPRISE CO., LTD); Manufacturer Part Number: C1206N101J102T
footprint CAP-1206 (1206 (3216M) Capacitor)
pins: 1, 2

## C1206N101J202T
designator C?  Capacitance: 100pF  (hidden comment: *)
Capacitor, Ceramic (MLCC), 100pF, ±5%, 2kV, C0G, ±5%, SMD 1206; Manufacturer: IHHEC(HOLY STONE ENTERPRISE CO., LTD); Manufacturer Part Number: C1206N101J202T
footprint CAP-1206 (1206 (3216M) Capacitor)
pins: 1, 2

## C1206N102J102T
designator C?  Capacitance: 1nF  (hidden comment: *)
Capacitor, Ceramic (MLCC), 1nF, ±5%, 1kV, C0G, ±5%, SMD 1206; Manufacturer: IHHEC(HOLY STONE ENTERPRISE CO., LTD); Manufacturer Part Number: C1206N102J102T
footprint CAP-1206 (1206 (3216M) Capacitor)
pins: 1, 2

## C1206N102J501T
designator C?  Capacitance: 1nF  (hidden comment: *)
Capacitor, Ceramic (MLCC), 1nF, ±5%, 500V, NP0, ±5%, SMD 1206; Manufacturer: IHHEC(HOLY STONE ENTERPRISE CO., LTD); Manufacturer Part Number: C1206N102J501T
footprint CAP-1206 (1206 (3216M) Capacitor)
pins: 1, 2

## C1206N102J631T
designator C?  Capacitance: 1nF  (hidden comment: *)
Capacitor, Ceramic (MLCC), 1nF, ±5%, 630V, NP0, ±5%, SMD 1206; Manufacturer: IHHEC(HOLY STONE ENTERPRISE CO., LTD); Manufacturer Part Number: C1206N102J631T
footprint CAP-1206 (1206 (3216M) Capacitor)
pins: 1, 2

## C1206N103J050T
designator C?  Capacitance: 10nF  (hidden comment: *)
Capacitor, Ceramic (MLCC), 10nF, ±5%, 50V, NP0, ±5%, SMD 1206; Manufacturer: IHHEC(HOLY STONE ENTERPRISE CO., LTD); Manufacturer Part Number: C1206N103J050T
footprint CAP-1206 (1206 (3216M) Capacitor)
pins: 1, 2

## C1206N103J101T
designator C?  Capacitance: 10nF  (hidden comment: *)
Capacitor, Ceramic (MLCC), 10nF, ±5%, 100V, NP0, ±5%, SMD 1206; Manufacturer: IHHEC(HOLY STONE ENTERPRISE CO., LTD); Manufacturer Part Number: C1206N103J101T
footprint CAP-1206 (1206 (3216M) Capacitor)
pins: 1, 2

## C1206N103K101T
designator C?  Capacitance: 10nF  (hidden comment: *)
Capacitor, Ceramic (MLCC), 10nF, ±10%, 100V, NP0, ±10%, SMD 1206; Manufacturer: IHHEC(HOLY STONE ENTERPRISE CO., LTD); Manufacturer Part Number: C1206N103K101T
footprint CAP-1206 (1206 (3216M) Capacitor)
pins: 1, 2

## C1206N104J050T
designator C?  Capacitance: 100nF  (hidden comment: *)
Capacitor, Ceramic (MLCC), 100nF, ±5%, 50V, NP0, ±5%, SMD 1206; Manufacturer: IHHEC(HOLY STONE ENTERPRISE CO., LTD); Manufacturer Part Number: C1206N104J050T
footprint CAP-1206 (1206 (3216M) Capacitor)
pins: 1, 2

## C1206N150J102T
designator C?  Capacitance: 15pF  (hidden comment: *)
Capacitor, Ceramic (MLCC), 15pF, ±5%, 1kV, C0G, ±5%, SMD 1206; Manufacturer: IHHEC(HOLY STONE ENTERPRISE CO., LTD); Manufacturer Part Number: C1206N150J102T
footprint CAP-1206 (1206 (3216M) Capacitor)
pins: 1, 2

## C1206N183K050T
designator C?  Capacitance: 18nF  (hidden comment: *)
Capacitor, Ceramic (MLCC), 18nF, ±10%, 50V, NP0, ±10%, SMD 1206; Manufacturer: IHHEC(HOLY STONE ENTERPRISE CO., LTD); Manufacturer Part Number: C1206N183K050T
footprint CAP-1206 (1206 (3216M) Capacitor)
pins: 1, 2

## C1206N220J102T
designator C?  Capacitance: 22pF  (hidden comment: *)
Capacitor, Ceramic (MLCC), 22pF, ±5%, 1kV, NP0, ±5%, SMD 1206; Manufacturer: IHHEC(HOLY STONE ENTERPRISE CO., LTD); Manufacturer Part Number: C1206N220J102T
footprint CAP-1206 (1206 (3216M) Capacitor)
pins: 1, 2

## C1206N221J102T
designator C?  Capacitance: 220pF  (hidden comment: *)
Capacitor, Ceramic (MLCC), 220pF, ±5%, 1kV, C0G, ±5%, SMD 1206; Manufacturer: IHHEC(HOLY STONE ENTERPRISE CO., LTD); Manufacturer Part Number: C1206N221J102T
footprint CAP-1206 (1206 (3216M) Capacitor)
pins: 1, 2

## C1206N221J202T
designator C?  Capacitance: 220pF  (hidden comment: *)
Capacitor, Ceramic (MLCC), 220pF, ±5%, 2kV, C0G, ±5%, SMD 1206; Manufacturer: IHHEC(HOLY STONE ENTERPRISE CO., LTD); Manufacturer Part Number: C1206N221J202T
footprint CAP-1206 (1206 (3216M) Capacitor)
pins: 1, 2

## C1206N222J050T
designator C?  Capacitance: 2.2nF  (hidden comment: *)
Capacitor, Ceramic (MLCC), 2.2nF, ±5%, 50V, NP0, ±5%, SMD 1206; Manufacturer: IHHEC(HOLY STONE ENTERPRISE CO., LTD); Manufacturer Part Number: C1206N222J050T
footprint CAP-1206 (1206 (3216M) Capacitor)
pins: 1, 2

## C1206N222J501T
designator C?  Capacitance: 2.2nF  (hidden comment: *)
Capacitor, Ceramic (MLCC), 2.2nF, ±5%, 500V, NP0, ±5%, SMD 1206; Manufacturer: IHHEC(HOLY STONE ENTERPRISE CO., LTD); Manufacturer Part Number: C1206N222J501T
footprint CAP-1206 (1206 (3216M) Capacitor)
pins: 1, 2

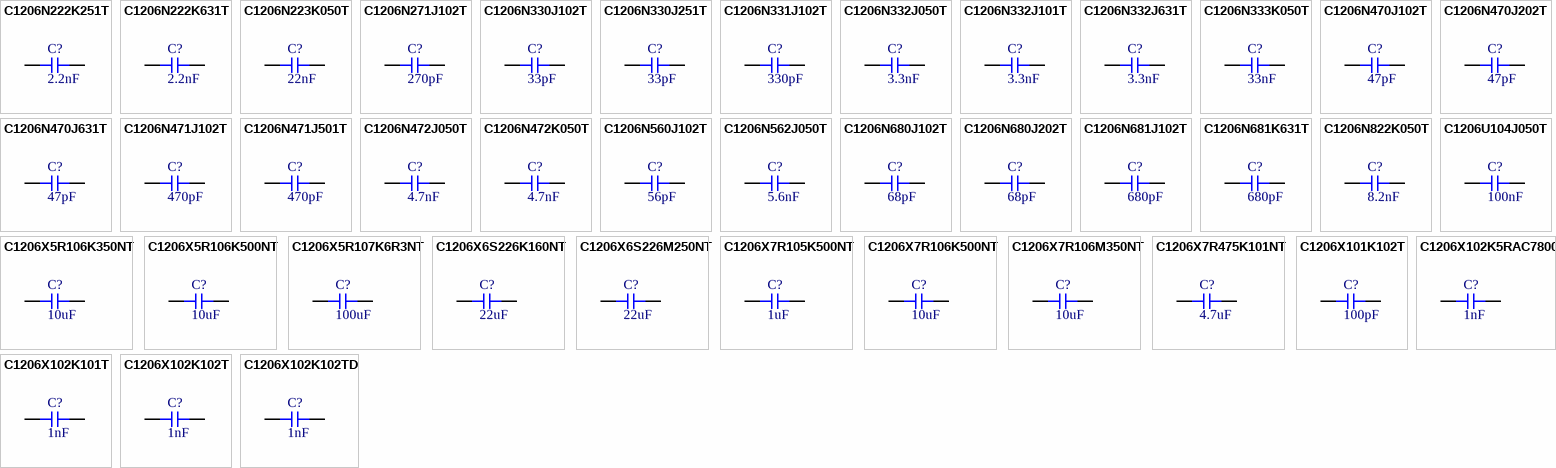
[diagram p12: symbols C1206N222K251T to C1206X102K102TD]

## C1206N222K251T
designator C?  Capacitance: 2.2nF  (hidden comment: *)
Capacitor, Ceramic (MLCC), 2.2nF, ±10%, 250V, NP0, ±10%, SMD 1206; Manufacturer: IHHEC(HOLY STONE ENTERPRISE CO., LTD); Manufacturer Part Number: C1206N222K251T
footprint CAP-1206 (1206 (3216M) Capacitor)
pins: 1, 2

## C1206N222K631T
designator C?  Capacitance: 2.2nF  (hidden comment: *)
Capacitor, Ceramic (MLCC), 2.2nF, ±10%, 630V, NP0, ±10%, SMD 1206; Manufacturer: IHHEC(HOLY STONE ENTERPRISE CO., LTD); Manufacturer Part Number: C1206N222K631T
footprint CAP-1206 (1206 (3216M) Capacitor)
pins: 1, 2

## C1206N223K050T
designator C?  Capacitance: 22nF  (hidden comment: *)
Capacitor, Ceramic (MLCC), 22nF, ±10%, 50V, NP0, ±10%, SMD 1206; Manufacturer: IHHEC(HOLY STONE ENTERPRISE CO., LTD); Manufacturer Part Number: C1206N223K050T
footprint CAP-1206 (1206 (3216M) Capacitor)
pins: 1, 2

## C1206N271J102T
designator C?  Capacitance: 270pF  (hidden comment: *)
Capacitor, Ceramic (MLCC), 270pF, ±5%, 1kV, NP0, ±5%, SMD 1206; Manufacturer: IHHEC(HOLY STONE ENTERPRISE CO., LTD); Manufacturer Part Number: C1206N271J102T
footprint CAP-1206 (1206 (3216M) Capacitor)
pins: 1, 2

## C1206N330J102T
designator C?  Capacitance: 33pF  (hidden comment: *)
Capacitor, Ceramic (MLCC), 33pF, ±5%, 1kV, C0G, ±5%, SMD 1206; Manufacturer: IHHEC(HOLY STONE ENTERPRISE CO., LTD); Manufacturer Part Number: C1206N330J102T
footprint CAP-1206 (1206 (3216M) Capacitor)
pins: 1, 2

## C1206N330J251T
designator C?  Capacitance: 33pF  (hidden comment: *)
Capacitor, Ceramic (MLCC), 33pF, ±5%, 250V, NP0, ±5%, SMD 1206; Manufacturer: IHHEC(HOLY STONE ENTERPRISE CO., LTD); Manufacturer Part Number: C1206N330J251T
footprint CAP-1206 (1206 (3216M) Capacitor)
pins: 1, 2

## C1206N331J102T
designator C?  Capacitance: 330pF  (hidden comment: *)
Capacitor, Ceramic (MLCC), 330pF, ±5%, 1kV, NP0, ±5%, SMD 1206; Manufacturer: IHHEC(HOLY STONE ENTERPRISE CO., LTD); Manufacturer Part Number: C1206N331J102T
footprint CAP-1206 (1206 (3216M) Capacitor)
pins: 1, 2

## C1206N332J050T
designator C?  Capacitance: 3.3nF  (hidden comment: *)
Capacitor, Ceramic (MLCC), 3.3nF, ±5%, 50V, NP0, ±5%, SMD 1206; Manufacturer: IHHEC(HOLY STONE ENTERPRISE CO., LTD); Manufacturer Part Number: C1206N332J050T
footprint CAP-1206 (1206 (3216M) Capacitor)
pins: 1, 2

## C1206N332J101T
designator C?  Capacitance: 3.3nF  (hidden comment: *)
Capacitor, Ceramic (MLCC), 3.3nF, ±5%, 100V, NP0, ±5%, SMD 1206; Manufacturer: IHHEC(HOLY STONE ENTERPRISE CO., LTD); Manufacturer Part Number: C1206N332J101T
footprint CAP-1206 (1206 (3216M) Capacitor)
pins: 1, 2

## C1206N332J631T
designator C?  Capacitance: 3.3nF  (hidden comment: *)
Capacitor, Ceramic (MLCC), 3.3nF, ±5%, 630V, NP0, ±5%, SMD 1206; Manufacturer: IHHEC(HOLY STONE ENTERPRISE CO., LTD); Manufacturer Part Number: C1206N332J631T
footprint CAP-1206 (1206 (3216M) Capacitor)
pins: 1, 2

## C1206N333K050T
designator C?  Capacitance: 33nF  (hidden comment: *)
Capacitor, Ceramic (MLCC), 33nF, ±10%, 50V, NP0, ±10%, SMD 1206; Manufacturer: IHHEC(HOLY STONE ENTERPRISE CO., LTD); Manufacturer Part Number: C1206N333K050T
footprint CAP-1206 (1206 (3216M) Capacitor)
pins: 1, 2

## C1206N470J102T
designator C?  Capacitance: 47pF  (hidden comment: *)
Capacitor, Ceramic (MLCC), 47pF, ±5%, 1kV, C0G, ±5%, SMD 1206; Manufacturer: IHHEC(HOLY STONE ENTERPRISE CO., LTD); Manufacturer Part Number: C1206N470J102T
footprint CAP-1206 (1206 (3216M) Capacitor)
pins: 1, 2

## C1206N470J202T
designator C?  Capacitance: 47pF  (hidden comment: *)
Capacitor, Ceramic (MLCC), 47pF, ±5%, 2kV, C0G, ±5%, SMD 1206; Manufacturer: IHHEC(HOLY STONE ENTERPRISE CO., LTD); Manufacturer Part Number: C1206N470J202T
footprint CAP-1206 (1206 (3216M) Capacitor)
pins: 1, 2

## C1206N470J631T
designator C?  Capacitance: 47pF  (hidden comment: *)
Capacitor, Ceramic (MLCC), 47pF, ±5%, 630V, NP0, ±5%, SMD 1206; Manufacturer: IHHEC(HOLY STONE ENTERPRISE CO., LTD); Manufacturer Part Number: C1206N470J631T
footprint CAP-1206 (1206 (3216M) Capacitor)
pins: 1, 2

## C1206N471J102T
designator C?  Capacitance: 470pF  (hidden comment: *)
Capacitor, Ceramic (MLCC), 470pF, ±5%, 1kV, C0G, ±5%, SMD 1206; Manufacturer: IHHEC(HOLY STONE ENTERPRISE CO., LTD); Manufacturer Part Number: C1206N471J102T
footprint CAP-1206 (1206 (3216M) Capacitor)
pins: 1, 2

## C1206N471J501T
designator C?  Capacitance: 470pF  (hidden comment: *)
Capacitor, Ceramic (MLCC), 470pF, ±5%, 500V, NP0, ±5%, SMD 1206; Manufacturer: IHHEC(HOLY STONE ENTERPRISE CO., LTD); Manufacturer Part Number: C1206N471J501T
footprint CAP-1206 (1206 (3216M) Capacitor)
pins: 1, 2

## C1206N472J050T
designator C?  Capacitance: 4.7nF  (hidden comment: *)
Capacitor, Ceramic (MLCC), 4.7nF, ±5%, 50V, NP0, ±5%, SMD 1206; Manufacturer: IHHEC(HOLY STONE ENTERPRISE CO., LTD); Manufacturer Part Number: C1206N472J050T
footprint CAP-1206 (1206 (3216M) Capacitor)
pins: 1, 2

## C1206N472K050T
designator C?  Capacitance: 4.7nF  (hidden comment: *)
Capacitor, Ceramic (MLCC), 4.7nF, ±10%, 50V, NP0, ±10%, SMD 1206; Manufacturer: IHHEC(HOLY STONE ENTERPRISE CO., LTD); Manufacturer Part Number: C1206N472K050T
footprint CAP-1206 (1206 (3216M) Capacitor)
pins: 1, 2

## C1206N560J102T
designator C?  Capacitance: 56pF  (hidden comment: *)
Capacitor, Ceramic (MLCC), 56pF, ±5%, 1kV, C0G, ±5%, SMD 1206; Manufacturer: IHHEC(HOLY STONE ENTERPRISE CO., LTD); Manufacturer Part Number: C1206N560J102T
footprint CAP-1206 (1206 (3216M) Capacitor)
pins: 1, 2

## C1206N562J050T
designator C?  Capacitance: 5.6nF  (hidden comment: *)
Capacitor, Ceramic (MLCC), 5.6nF, ±5%, 50V, NP0, ±5%, SMD 1206; Manufacturer: IHHEC(HOLY STONE ENTERPRISE CO., LTD); Manufacturer Part Number: C1206N562J050T
footprint CAP-1206 (1206 (3216M) Capacitor)
pins: 1, 2

## C1206N680J102T
designator C?  Capacitance: 68pF  (hidden comment: *)
Capacitor, Ceramic (MLCC), 68pF, ±5%, 1kV, C0G, ±5%, SMD 1206; Manufacturer: IHHEC(HOLY STONE ENTERPRISE CO., LTD); Manufacturer Part Number: C1206N680J102T
footprint CAP-1206 (1206 (3216M) Capacitor)
pins: 1, 2

## C1206N680J202T
designator C?  Capacitance: 68pF  (hidden comment: *)
Capacitor, Ceramic (MLCC), 68pF, ±5%, 2kV, NP0, ±5%, SMD 1206; Manufacturer: IHHEC(HOLY STONE ENTERPRISE CO., LTD); Manufacturer Part Number: C1206N680J202T
footprint CAP-1206 (1206 (3216M) Capacitor)
pins: 1, 2

## C1206N681J102T
designator C?  Capacitance: 680pF  (hidden comment: *)
Capacitor, Ceramic (MLCC), 680pF, ±5%, 1kV, C0G, ±5%, SMD 1206; Manufacturer: IHHEC(HOLY STONE ENTERPRISE CO., LTD); Manufacturer Part Number: C1206N681J102T
footprint CAP-1206 (1206 (3216M) Capacitor)
pins: 1, 2

## C1206N681K631T
designator C?  Capacitance: 680pF  (hidden comment: *)
Capacitor, Ceramic (MLCC), 680pF, ±10%, 630V, NP0, ±10%, SMD 1206; Manufacturer: IHHEC(HOLY STONE ENTERPRISE CO., LTD); Manufacturer Part Number: C1206N681K631T
footprint CAP-1206 (1206 (3216M) Capacitor)
pins: 1, 2

## C1206N822K050T
designator C?  Capacitance: 8.2nF  (hidden comment: *)
Capacitor, Ceramic (MLCC), 8.2nF, ±10%, 50V, NP0, ±10%, SMD 1206; Manufacturer: IHHEC(HOLY STONE ENTERPRISE CO., LTD); Manufacturer Part Number: C1206N822K050T
footprint CAP-1206 (1206 (3216M) Capacitor)
pins: 1, 2

## C1206U104J050T
designator C?  Capacitance: 100nF  (hidden comment: *)
Capacitor, Ceramic (MLCC), 100nF, ±5%, 50V, U2J, ±5%, SMD 1206; Manufacturer: IHHEC(HOLY STONE ENTERPRISE CO., LTD); Manufacturer Part Number: C1206U104J050T
footprint CAP-1206 (1206 (3216M) Capacitor)
pins: 1, 2

## C1206X5R106K350NT
designator C?  Capacitance: 10uF  (hidden comment: *)
Capacitor, Ceramic (MLCC), 10uF, ±10%, 35V, ±10%, SMD 1206; Manufacturer: SANYEAR; Manufacturer Part Number: C1206X5R106K350NT
footprint CAP-1206 (1206 (3216M) Capacitor)
pins: 1, 2

## C1206X5R106K500NT
designator C?  Capacitance: 10uF  (hidden comment: *)
Capacitor, Ceramic (MLCC), 10uF, ±10%, 50V, X5R, ±10%, SMD 1206; Manufacturer: SANYEAR; Manufacturer Part Number: C1206X5R106K500NT
footprint CAP-1206 (1206 (3216M) Capacitor)
pins: 1, 2

## C1206X5R107K6R3NT
designator C?  Capacitance: 100uF  (hidden comment: *)
Capacitor, Ceramic (MLCC), 100uF, ±10%, 6.3V, ±10%, SMD 1206; Manufacturer: SANYEAR; Manufacturer Part Number: C1206X5R107K6R3NT
footprint CAP-1206 (1206 (3216M) Capacitor)
pins: 1, 2

## C1206X6S226K160NT
designator C?  Capacitance: 22uF  (hidden comment: *)
Capacitor, Ceramic (MLCC), 22uF, ±10%, 16V, ±10%, SMD 1206; Manufacturer: SANYEAR; Manufacturer Part Number: C1206X6S226K160NT
footprint CAP-1206 (1206 (3216M) Capacitor)
pins: 1, 2

## C1206X6S226M250NT
designator C?  Capacitance: 22uF  (hidden comment: *)
Capacitor, Ceramic (MLCC), 22uF, ±20%, 25V, ±20%, SMD 1206; Manufacturer: SANYEAR; Manufacturer Part Number: C1206X6S226M250NT
footprint CAP-1206 (1206 (3216M) Capacitor)
pins: 1, 2

## C1206X7R105K500NT
designator C?  Capacitance: 1uF  (hidden comment: *)
Capacitor, Ceramic (MLCC), 1uF, ±10%, 50V, X7R, ±10%, SMD 1206; Manufacturer: SANYEAR; Manufacturer Part Number: C1206X7R105K500NT
footprint CAP-1206 (1206 (3216M) Capacitor)
pins: 1, 2

## C1206X7R106K500NT
designator C?  Capacitance: 10uF  (hidden comment: *)
Capacitor, Ceramic (MLCC), 10uF, ±10%, 50V, ±10%, SMD 1206; Manufacturer: SANYEAR; Manufacturer Part Number: C1206X7R106K500NT
footprint CAP-1206 (1206 (3216M) Capacitor)
pins: 1, 2

## C1206X7R106M350NT
designator C?  Capacitance: 10uF  (hidden comment: *)
Capacitor, Ceramic (MLCC), 10uF, ±20%, 35V, ±20%, SMD 1206; Manufacturer: SANYEAR; Manufacturer Part Number: C1206X7R106M350NT
footprint CAP-1206 (1206 (3216M) Capacitor)
pins: 1, 2

## C1206X7R475K101NT
designator C?  Capacitance: 4.7uF  (hidden comment: *)
Capacitor, Ceramic (MLCC), 4.7uF, ±10%, 100V, ±10%, SMD 1206; Manufacturer: SANYEAR; Manufacturer Part Number: C1206X7R475K101NT
footprint CAP-1206 (1206 (3216M) Capacitor)
pins: 1, 2

## C1206X101K102T
designator C?  Capacitance: 100pF  (hidden comment: *)
Capacitor, Ceramic (MLCC), 100pF, ±10%, 1kV, X7R, ±10%, SMD 1206; Manufacturer: IHHEC(HOLY STONE ENTERPRISE CO., LTD); Manufacturer Part Number: C1206X101K102T
footprint CAP-1206 (1206 (3216M) Capacitor)
pins: 1, 2

## C1206X102K5RAC7800
designator C?  Capacitance: 1nF  (hidden comment: *)
Capacitor, Ceramic (MLCC), 1nF, ±10%, 50V, X7R, ±10%, SMD 1206; Manufacturer: KEMET; Manufacturer Part Number: C1206X102K5RAC7800
footprint CAP-1206 (1206 (3216M) Capacitor)
pins: 1, 2

## C1206X102K101T
designator C?  Capacitance: 1nF  (hidden comment: *)
Capacitor, Ceramic (MLCC), 1nF, ±10%, 100V, X7R, ±10%, SMD 1206; Manufacturer: IHHEC(HOLY STONE ENTERPRISE CO., LTD); Manufacturer Part Number: C1206X102K101T
footprint CAP-1206 (1206 (3216M) Capacitor)
pins: 1, 2

## C1206X102K102T
designator C?  Capacitance: 1nF  (hidden comment: *)
Capacitor, Ceramic (MLCC), 1nF, ±10%, 1kV, X7R, ±10%, SMD 1206; Manufacturer: IHHEC(HOLY STONE ENTERPRISE CO., LTD); Manufacturer Part Number: C1206X102K102T
footprint CAP-1206 (1206 (3216M) Capacitor)
pins: 1, 2

## C1206X102K102TD
designator C?  Capacitance: 1nF  (hidden comment: *)
Capacitor, Ceramic (MLCC), 1nF, ±10%, 1kV, X7R, ±10%, SMD 1206; Manufacturer: IHHEC(HOLY STONE ENTERPRISE CO., LTD); Manufacturer Part Number: C1206X102K102TD
footprint CAP-1206 (1206 (3216M) Capacitor)
pins: 1, 2

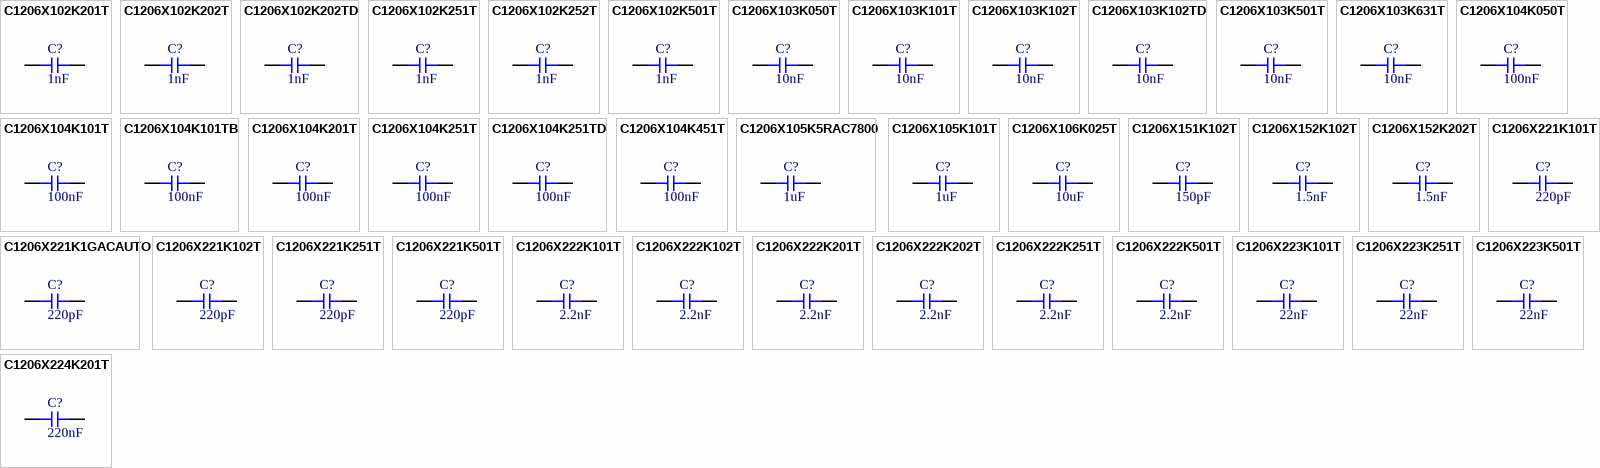
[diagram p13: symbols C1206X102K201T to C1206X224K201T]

## C1206X102K201T
designator C?  Capacitance: 1nF  (hidden comment: *)
Capacitor, Ceramic (MLCC), 1nF, ±10%, 200V, X7R, ±10%, SMD 1206; Manufacturer: IHHEC(HOLY STONE ENTERPRISE CO., LTD); Manufacturer Part Number: C1206X102K201T
footprint CAP-1206 (1206 (3216M) Capacitor)
pins: 1, 2

## C1206X102K202T
designator C?  Capacitance: 1nF  (hidden comment: *)
Capacitor, Ceramic (MLCC), 1nF, ±10%, 2kV, X7R, ±10%, SMD 1206; Manufacturer: IHHEC(HOLY STONE ENTERPRISE CO., LTD); Manufacturer Part Number: C1206X102K202T
footprint CAP-1206 (1206 (3216M) Capacitor)
pins: 1, 2

## C1206X102K202TD
designator C?  Capacitance: 1nF  (hidden comment: *)
Capacitor, Ceramic (MLCC), 1nF, ±10%, 2kV, X7R, ±10%, SMD 1206; Manufacturer: IHHEC(HOLY STONE ENTERPRISE CO., LTD); Manufacturer Part Number: C1206X102K202TD
footprint CAP-1206 (1206 (3216M) Capacitor)
pins: 1, 2

## C1206X102K251T
designator C?  Capacitance: 1nF  (hidden comment: *)
Capacitor, Ceramic (MLCC), 1nF, ±10%, 250V, X7R, ±10%, SMD 1206; Manufacturer: IHHEC(HOLY STONE ENTERPRISE CO., LTD); Manufacturer Part Number: C1206X102K251T
footprint CAP-1206 (1206 (3216M) Capacitor)
pins: 1, 2

## C1206X102K252T
designator C?  Capacitance: 1nF  (hidden comment: *)
Capacitor, Ceramic (MLCC), 1nF, ±10%, 2.5kV, X7R, ±10%, SMD 1206; Manufacturer: IHHEC(HOLY STONE ENTERPRISE CO., LTD); Manufacturer Part Number: C1206X102K252T
footprint CAP-1206 (1206 (3216M) Capacitor)
pins: 1, 2

## C1206X102K501T
designator C?  Capacitance: 1nF  (hidden comment: *)
Capacitor, Ceramic (MLCC), 1nF, ±10%, 500V, X7R, ±10%, SMD 1206; Manufacturer: IHHEC(HOLY STONE ENTERPRISE CO., LTD); Manufacturer Part Number: C1206X102K501T
footprint CAP-1206 (1206 (3216M) Capacitor)
pins: 1, 2

## C1206X103K050T
designator C?  Capacitance: 10nF  (hidden comment: *)
Capacitor, Ceramic (MLCC), 10nF, ±10%, 50V, X7R, ±10%, SMD 1206; Manufacturer: IHHEC(HOLY STONE ENTERPRISE CO., LTD); Manufacturer Part Number: C1206X103K050T
footprint CAP-1206 (1206 (3216M) Capacitor)
pins: 1, 2

## C1206X103K101T
designator C?  Capacitance: 10nF  (hidden comment: *)
Capacitor, Ceramic (MLCC), 10nF, ±10%, 100V, X7R, ±10%, SMD 1206; Manufacturer: IHHEC(HOLY STONE ENTERPRISE CO., LTD); Manufacturer Part Number: C1206X103K101T
footprint CAP-1206 (1206 (3216M) Capacitor)
pins: 1, 2

## C1206X103K102T
designator C?  Capacitance: 10nF  (hidden comment: *)
Capacitor, Ceramic (MLCC), 10nF, ±10%, 1kV, X7R, ±10%, SMD 1206; Manufacturer: IHHEC(HOLY STONE ENTERPRISE CO., LTD); Manufacturer Part Number: C1206X103K102T
footprint CAP-1206 (1206 (3216M) Capacitor)
pins: 1, 2

## C1206X103K102TD
designator C?  Capacitance: 10nF  (hidden comment: *)
Capacitor, Ceramic (MLCC), 10nF, ±10%, 1kV, X7R, ±10%, SMD 1206; Manufacturer: IHHEC(HOLY STONE ENTERPRISE CO., LTD); Manufacturer Part Number: C1206X103K102TD
footprint CAP-1206 (1206 (3216M) Capacitor)
pins: 1, 2

## C1206X103K501T
designator C?  Capacitance: 10nF  (hidden comment: *)
Capacitor, Ceramic (MLCC), 10nF, ±10%, 500V, X7R, ±10%, SMD 1206; Manufacturer: IHHEC(HOLY STONE ENTERPRISE CO., LTD); Manufacturer Part Number: C1206X103K501T
footprint CAP-1206 (1206 (3216M) Capacitor)
pins: 1, 2

## C1206X103K631T
designator C?  Capacitance: 10nF  (hidden comment: *)
Capacitor, Ceramic (MLCC), 10nF, ±10%, 630V, X7R, ±10%, SMD 1206; Manufacturer: IHHEC(HOLY STONE ENTERPRISE CO., LTD); Manufacturer Part Number: C1206X103K631T
footprint CAP-1206 (1206 (3216M) Capacitor)
pins: 1, 2

## C1206X104K050T
designator C?  Capacitance: 100nF  (hidden comment: *)
Capacitor, Ceramic (MLCC), 100nF, ±10%, 50V, X7R, ±10%, SMD 1206; Manufacturer: IHHEC(HOLY STONE ENTERPRISE CO., LTD); Manufacturer Part Number: C1206X104K050T
footprint CAP-1206 (1206 (3216M) Capacitor)
pins: 1, 2

## C1206X104K101T
designator C?  Capacitance: 100nF  (hidden comment: *)
Capacitor, Ceramic (MLCC), 100nF, ±10%, 100V, X7R, ±10%, SMD 1206; Manufacturer: IHHEC(HOLY STONE ENTERPRISE CO., LTD); Manufacturer Part Number: C1206X104K101T
footprint CAP-1206 (1206 (3216M) Capacitor)
pins: 1, 2

## C1206X104K101TB
designator C?  Capacitance: 100nF  (hidden comment: *)
Capacitor, Ceramic (MLCC), 100nF, ±10%, 100V, X7R, ±10%, SMD 1206; Manufacturer: IHHEC(HOLY STONE ENTERPRISE CO., LTD); Manufacturer Part Number: C1206X104K101TB
footprint CAP-1206 (1206 (3216M) Capacitor)
pins: 1, 2

## C1206X104K201T
designator C?  Capacitance: 100nF  (hidden comment: *)
Capacitor, Ceramic (MLCC), 100nF, ±10%, 200V, X7R, ±10%, SMD 1206; Manufacturer: IHHEC(HOLY STONE ENTERPRISE CO., LTD); Manufacturer Part Number: C1206X104K201T
footprint CAP-1206 (1206 (3216M) Capacitor)
pins: 1, 2

## C1206X104K251T
designator C?  Capacitance: 100nF  (hidden comment: *)
Capacitor, Ceramic (MLCC), 100nF, ±10%, 250V, X7R, ±10%, SMD 1206; Manufacturer: IHHEC(HOLY STONE ENTERPRISE CO., LTD); Manufacturer Part Number: C1206X104K251T
footprint CAP-1206 (1206 (3216M) Capacitor)
pins: 1, 2

## C1206X104K251TD
designator C?  Capacitance: 100nF  (hidden comment: *)
Capacitor, Ceramic (MLCC), 100nF, ±10%, 250V, X7R, ±10%, SMD 1206; Manufacturer: IHHEC(HOLY STONE ENTERPRISE CO., LTD); Manufacturer Part Number: C1206X104K251TD
footprint CAP-1206 (1206 (3216M) Capacitor)
pins: 1, 2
